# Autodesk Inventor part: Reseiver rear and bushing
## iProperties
Created: 2006-04
Part Number: Reseiver rear and bushing
Document SubType Name: Modeling
Designer: Калинин
Author: Калинин
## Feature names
1. Вращение1 [Revolution]
2. Выдавливание1 [Extrusion]
3. Выдавливание2 [Extrusion]
4. Сопряжение1 [Fillet]
5. Фаска2 [Chamfer]
6. Сопряжение2 [Fillet]
7. Сопряжение3 [Fillet]
8. Сопряжение4 [Fillet]
9. Сопряжение5 [Fillet]
10. Фаска3 [Chamfer]
11. Сопряжение6 [Fillet]
12. Сопряжение7 [Fillet]
13. Сопряжение8 [Fillet]
14. Сопряжение9 [Fillet]
